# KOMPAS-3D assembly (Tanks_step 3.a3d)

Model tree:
1. Plane XY
2. Plane ZX
3. Plane ZY
4. X Axis
5. Y Axis
6. Z Axis
7. Origin
8. Polyline:418
9. Polyline:448
10. Polyline:538
11. Polyline:568
12. Polyline:569
13. Polyline:570
14. Route 1  (labels: Route 1)
15. Point:1
     X = -6791.83; Y = -1500; Z = 1.7112e-08; Coordinate.X = -6791.83; Coordinate.Y = -1500; Coordinate.Z = 1.7112e-08
16. Point:2
     X = -1606; Y = -500; Move.X = -500; Distance = 500
17. Point:3
     X = -1606; Y = -2500; Z = 700; Move.X = -500; Move.Z = 4.09273e-09; Distance = 500
18. Point:9  (labels: C:\Program Files\ASCON\KOMPAS-3D V10\Sys\graphic.lyt; Pipe Dn 50; Pipe_Tanks_step 2_70.m3d; Pipe_Tanks_step 2_72.m3d)
     X = -3769.83; Y = 762.724; Z = 3112; Move.Z = 500; Distance = 500; Orientation = 2; Orientation = 1; Orientation = 1; Orientation = 1; Orientation = 1; Orientation = 1; Orientation = 1; Orientation = 1; Orientation = 1; Orientation = 1; Orientation = 1; Orientation = 1; Orientation = 1; Orientation = 1

Referenced files in C:\Documents and Settings\kashirsky\Мои документы\Camtasia Studio\Pipelines3D\Tanks\: Tank 2.a3d, Tank 1.a3d, Piping_Joint_150_1000.m3d, Piping_Flange_150_1000.m3d, Piping_Joint_50_1000.m3d, Piping_Flange_50_1000.m3d
Referenced files in C:\Program Files\ASCON\KOMPAS-3D V10\Libs\Piping\Equipment\Valve\: Piping_Valve_50_1000.m3d
Referenced files in C:\Program Files\ASCON\KOMPAS-3D V10\Libs\Piping\LOAD\: Piping_C_Bend_90_50_1000.m3d, Piping_C_TBend_50_1000.m3d
Referenced files in C:\Documents and Settings\kashirsky\Мои документы\Camtasia Studio\Pipelines3D\Tanks\Tanks_step 2_Pipes\: Pipe_Tanks_step 2_70.m3d, Pipe_Tanks_step 2_71.m3d, Pipe_Tanks_step 2_72.m3d, Pipe_Tanks_step 2_73.m3d, Pipe_Tanks_step 2_74.m3d, Pipe_Tanks_step 2_75.m3d, Pipe_Tanks_step 2_76.m3d, Pipe_Tanks_step 2_77.m3d, Pipe_Tanks_step 2_78.m3d, Pipe_Tanks_step 2_79.m3d, Pipe_Tanks_step 2_80.m3d, Pipe_Tanks_step 2_81.m3d, Pipe_Tanks_step 2_82.m3d, Pipe_Tanks_step 2_83.m3d, Pipe_Tanks_step 2_84.m3d, Pipe_Tanks_step 2_85.m3d, Pipe_Tanks_step 2_86.m3d, Pipe_Tanks_step 2_87.m3d, Pipe_Tanks_step 2_88.m3d, Pipe_Tanks_step 2_89.m3d
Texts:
  Three Point Plane
  Plane at Angle
  Line and Point Plane
  Axis through Two Vertices
  Axis of Feature
  Axis of Conical Surface
  Axis through Edge
  Trim by Surface
  Trim by Sketch
  Intersection Axis of Two Planes
  Two Line Plane
  Line and Face Plane
  Pattern by Sample
  Point in CM
  Feature with No History
  Linear Dimension from Line to Point
  Surface Finish Symbol
  Geometric Tolerance Symbol
  Текст на чертеже
  Линия-выноска #1
  Линия-выноска #2
  Линия-выноска #3
  Отклонения формы и база
  Марка координационной оси
  Марка/позиционное обозначение с линией-выноской
  Марка/позиционное обозначение на линии
  Марка/позиционное обозначение без линии-выноски
  Tank 2
  Tank 1
  Joint Dn 150
  Steel ASTM A295
  Flange Dn 150
  Прокладка Dy 50
  Flange Dn 50
  Bend 90 Dn 50
  T-Bend Dn 50
  Трубы - объекты
  Pipe Dn 50
  Трубы - описания
  Элементы - объекты
  Элементы - описания
  Pipelines 3D
  Valve Dy 50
